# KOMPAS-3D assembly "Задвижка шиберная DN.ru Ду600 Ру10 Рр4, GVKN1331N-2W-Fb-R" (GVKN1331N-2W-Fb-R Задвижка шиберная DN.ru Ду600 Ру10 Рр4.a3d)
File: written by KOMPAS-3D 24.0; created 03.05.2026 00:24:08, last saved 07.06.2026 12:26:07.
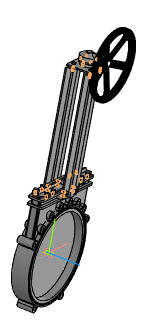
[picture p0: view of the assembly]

Document properties: Автор: DN.ru; Полное имя файла: E:\Работа\Зайцев\АУТСОРС\Даня\GVKN1331N-2W-Fb-R Задвижка шиберная DN.ru Ду400-600 Ру4-6\исходные материалы\DN600\GVKN1331N-2W-Fb-R Задвижка шиберная DN.ru Ду600 Ру10 Рр4.a3d

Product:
- Component [detail]: 1  | qty 1  | pos. 1  | Масса: 18.2; Раздел спецификации: Прочие изделия; Примечание: D050-23732; Автор: R2D2; source file: GVKN1331N-2W-Fb-R Задвижка шиберная DN.ru Ду600 Ру10 Рр4.m3d
- Component [detail]: Деталь 2  | qty 1  | pos. 2  | Масса: 18.896536; Автор: mrdid; additional columns: Типовые; source file: Деталь 2 - Деталь 2.m3d
- Part/product: Задвижка шиберная DN.ru Ду600 Ру10 Рр4  | designation GVKN1331N-2W-Fb-R
    Масса: 252
    Раздел спецификации: Прочие изделия
    Примечание: D040-07325

Referenced files in E:\Работа\Зайцев\АУТСОРС\Даня\GVKN1331N-2W-Fb-R Задвижка шиберная DN.ru Ду400-600 Ру4-6\исходные материалы\DN600\: Деталь 2 - Деталь 2.m3d, GVKN1331N-2W-Fb-R Задвижка шиберная DN.ru Ду600 Ру10 Рр4.m3d
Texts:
  GVKN1331N-2W-Fb-R
  Деталь 2 Деталь 2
